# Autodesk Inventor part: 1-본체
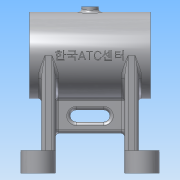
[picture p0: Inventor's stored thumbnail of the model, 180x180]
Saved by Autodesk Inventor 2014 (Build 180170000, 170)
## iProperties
Created: 2015-11
Part Number: 1-본체
Material: 알루미늄 6061
Document SubType Name: Modeling
Designer: 103-18
Mass: 359.155 g
Surface Area: 459.471 cm^2
Volume: 132.53 cm^3
Density: 2.71 g/cm^3
Appearance: 알루미늄 - 평지
Author: 103-18
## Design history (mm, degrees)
sketch "스케치1"
  geometry: L1 (0, 0)-(70, 0); L2 (0, 16)-(12, 16); L3 (12, 16)-(12, 14); L4 (12, 14)-(14, 14); L5 (14, 14)-(14, 21); L6 (14, 21)-(56, 21); L7 (56, 21)-(56, 14); L8 (56, 14)-(58, 14); L9 (58, 14)-(58, 16); L10 (58, 16)-(70, 16); L11 (70, 16)-(70, 25); L12 (70, 25)-(0, 25); L13 (0, 25)-(0, 16)
  constraints: 26 end point, 10 parallel, 2 vertical alignment, 1 collinear, 1 horizontal, 1 perpendicular
  dimensions: "d0" = 70 distance of L1.start L1.end; "d1" = 28 diameter of L4 L1; "d2" = 28 diameter of L8 L1; "d3" = 32 diameter of L10 L1; "d4" = 32 diameter of L2 L1; "d5" = 42 diameter of L6 L1; "d6" = 50 diameter of L12 L1; "d7" = 12 distance of L9.end L10.end; "d8" = 2 distance of L7.end L8.end; "d9" = 42 distance of L5.end L6.end; "d10" = 2 distance of L3.end L4.end
revolve "회전1" sketch "스케치1" stored, may be unused: angle "d11" = 90 deg
node "작업 평면1"
sketch "스케치2"
  geometry: C1 r 5 at (35, 0); 1 further point
  constraints: 1 centre point, 1 horizontal alignment
  dimensions: "d13" = 35 distance of C1.centre point (0, 0); "d14" = 10 diameter of C1
extrude "돌출1" join sketch "스케치2" stored distance "d15" = 10; taper "d16" = 0 deg
hole "구멍1" diameter "d19" = 5.188; stored, may be unused: countersink angle "d23" = 90 deg, drill point angle "d25" = 118 deg; dims "d17" = 10, "d18" = 10, "d20" = 6, "d21" = 4, "d22" = 2, "d24" = 8
sketch "스케치3"
  geometry: C1 r 25 at (0, 0) reference; C2 r 16 at (0, 0) reference; A1 r 20 centre (0, 0) between (0, 20) and (-20, 0); 2 further points
  constraints: 4 point on circle, 2 horizontal alignment, 2 vertical alignment, 1 centre point, 1 coincident
  dimensions: "d26" = 40 diameter of A1
hole "구멍2" sketch "스케치3" at (0, 20), (-20, 0), (0, -20), (20, 0) diameter "d27" = 3.242; stored, may be unused: countersink angle "d31" = 90 deg, drill point angle "d33" = 118 deg; dims "d28" = 8, "d29" = 4, "d30" = 2, "d32" = 10
node "작업 평면2"
node "작업 평면4"
  node "작업 평면3"
sketch "스케치4"
  geometry: C1 r 6 at (35, 0); 1 further point
  constraints: 1 centre point, 1 horizontal alignment
  dimensions: "d36" = 12 diameter of C1; "d37" = 35 distance of C1.centre point (0, 0)
extrude "돌출2" join sketch "스케치4" stored distance "d38" = 10; taper "d39" = 0 deg
hole "구멍3" diameter "d42" = 5.188; stored, may be unused: countersink angle "d46" = 90 deg, drill point angle "d48" = 118 deg; dims "d40" = 10, "d41" = 10, "d43" = 8, "d44" = 4, "d45" = 2, "d47" = 10
node "작업 평면5"
sketch "스케치5"
  geometry: L1 (-75, 40)-(-75, -40); L2 (-55, -40)-(-55, 40); L3 (-15, 40)-(-15, -40); L4 (5, -40)-(5, 40); L5 (0, 25)-(-70, 25) reference; L6 (-70, 25)-(0, 25); L7 (0, 25)-(0, -25) reference; L8 (-70, 25)-(-70, -25) reference; A1 r 10 centre (-65, -40) between (-75, -40) and (-55, -40); A2 r 10 centre (-65, 40) between (-55, 40) and (-75, 40); A3 r 10 centre (-5, -40) between (-15, -40) and (5, -40); A4 r 10 centre (-5, 40) between (5, 40) and (-15, 40); 6 further points; 1 other entity
  constraints: 10 end point, 8 point on circle, 8 tangent, 4 centre point, 4 equal length, 4 midpoint, 2 horizontal alignment, 1 equal radius, 1 parallel, 1 vertical, 1 other
  dimensions: "d50" = 10 radius of A2; "d51" = 80 distance of A1.centre A2.centre; "d52" = 80 distance of L4.end L1.start; "d53" = 40 distance from line of L4 point (-35, 14)
extrude "돌출3" join sketch "스케치5" distance "d54" = 10; taper "d55" = 0 deg
sketch "스케치6"
  geometry: C1 r 10 at (65, 40); A1 r 10 centre (65, 40) between (75, 40) and (55, 40) reference; 1 further point
  constraints: 1 centre point, 1 coincident, 1 concentric
extrude "돌출4" join sketch "스케치6" distance "d56" = 3; taper "d57" = 0 deg
hole "구멍4" diameter "d60" = 6; stored, may be unused: countersink angle "d64" = 90 deg, drill point angle "d66" = 118 deg; dims "d58" = 10, "d59" = 10, "d61" = 8, "d62" = 12, "d63" = 4, "d65" = 10
sketch "스케치7"
  geometry: L1 (75, -40)-(75, 40) reference; L2 (55, 40)-(55, -40) reference; L3 (55, 25)-(63, 25); L4 (63, 25)-(63, -25); L5 (63, -25)-(55, -25); L6 (55, -25)-(55, 25); 3 further points
  constraints: 8 end point, 2 midpoint, 2 parallel, 1 horizontal, 1 horizontal alignment, 1 perpendicular, 1 point on line
  dimensions: "d67" = 8 distance of L3.start L3.end; "d68" = 50 distance of L3.end L4.end
extrude "돌출5" join sketch "스케치7" stored distance "d69" = 3; taper "d70" = 0 deg
node "작업 평면6"
sketch "스케치8"
  geometry: L1 (15, 40)-(15, -40) reference; L2 (55, -40)-(55, 40) reference; L3 (15, 4)-(55, 4); L4 (55, 4)-(55, -4); L5 (55, -4)-(15, -4); L6 (15, -4)-(15, 4); 3 further points
  constraints: 8 end point, 2 midpoint, 2 parallel, 2 point on line, 1 coincident, 1 horizontal, 1 perpendicular
  dimensions: "d72" = 8 distance of L5.end L3.start
extrude "돌출6" join sketch "스케치8" stored distance "d73" = 3; taper "d74" = 0 deg
sketch "스케치9"
  geometry: L1 (0, 20.322)-(40, 20.322) reference; L2 (40, 20.322)-(40, 0) reference; L3 (12, 13.5)-(28, 13.5); L4 (28, 6.5)-(12, 6.5); L5 (15, 73)-(25, 73) reference; L6 (-15, 70)-(55, 70) reference; L7 (-20, -23)-(0, -23) reference; A1 r 3.5 centre (28, 10) between (28, 6.5) and (28, 13.5); A2 r 3.5 centre (12, 10) between (12, 13.5) and (12, 6.5); 3 further points
  constraints: 4 end point, 4 point on circle, 4 tangent, 2 centre point, 2 midpoint, 1 parallel, 1 perpendicular, 1 vertical alignment
  dimensions: "d75" = 23 dimension on A1 A2; "d76" = 33 distance from line of A2.centre L7; "d77" = 3.5 radius of A1
extrude "돌출7" cut sketch "스케치9" stored distance "d78" = 3; taper "d79" = 0 deg
node "작업 평면7"
sketch "스케치10"
  geometry: L1 (-35, 25)-(35, 25) reference; L2 (-35, -25)-(-35, 25) reference; 2 further points
  constraints: 1 horizontal alignment, 1 other
  dimensions: "d80" = 35 distance from line of point (0, 0) L2
feature "엠보싱1" sketch "스케치10" dims "d0" = 70, "d1" = 28, "d2" = 28, "d3" = 32, "d4" = 32, "d5" = 42, "d6" = 50, "d7" = 12, "d8" = 2, "d9" = 42, "d10" = 2, "d81" = 0.5, "d82" = 0
fillet "모깎기1" dims "d83" = 2
fillet "모깎기2" dims "d84" = 2
fillet "모깎기3" dims "d85" = 2
fillet "모깎기4" dims "d86" = 2
fillet "모깎기6" dims "d88" = 2
fillet "모깎기9" dims "d91" = 2
fillet "모깎기7" dims "d89" = 2
fillet "모깎기10" dims "d92" = 2
fillet "모깎기11" dims "d93" = 3, "d94" = 0.3
fillet "모깎기12" dims "d95" = 0.3
chamfer "모따기1" distance "d96" = 1; stored, may be unused: second distance "d97" = 2, angle "d98" = 45 deg
node "솔리드1"
mirror "대칭1"
mirror "대칭2"
mirror "대칭3"
mirror "대칭4"
other parameters: "d12" = 28, "d34" = -60 deg, "d35" = 28, "d49" = -68, "d71" = -45
